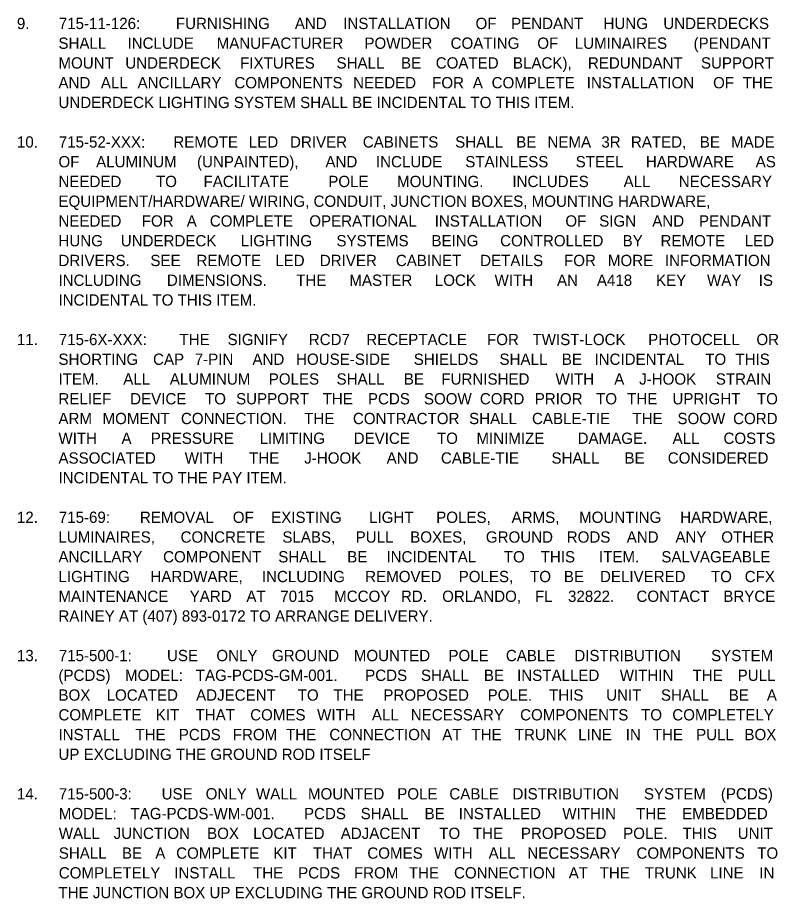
# Model space of a CAD drawing. Extents: x -55 to 2471539, y -90 to 3608906.
# Drawn here: x 544 to 1015, y 2826 to 3372 of the extents above; entities that cross this region are included whole.
import ezdxf

# ---------------------------------------------------------------- set-up
doc = ezdxf.new("R2010")
doc.units = 0
doc.layers.add('XSCell', color=7, linetype='Continuous')

msp = doc.modelspace()

# ---------------------------------------------------------------- texts
at = {"layer": 'XSCell'}
for s, p in [('9.', (543.22, 3365.2)), ('715-11-126: ', (569.17, 3365.2)), ('FURNISHING ', (641.75, 3365.2)), ('AND ', (715.49, 3365.2)), ('INSTALLATION ', (745.48, 3365.2)), ('OF ', (827.49, 3365.2)), ('PENDANT ', (849.52, 3365.2)), ('HUNG ', (906.82, 3365.2)), ('UNDERDECKS ', (943.89, 3365.2)), ('SHALL ', (568.97, 3352.95)), ('INCLUDE ', (611.77, 3352.95)), ('MANUFACTURER ', (667.02, 3352.95)), ('POWDER ', (758.61, 3352.95)), ('COATING ', (812.04, 3352.95)), ('OF ', (865.78, 3352.95)), ('LUMINAIRES ', (889.02, 3352.95)), ('(PENDANT ', (962.64, 3352.95)), ('MOUNT ', (568.97, 3340.7)), ('UNDERDECK ', (610.39, 3340.7)), ('FIXTURES ', (681.58, 3340.7)), ('SHALL ', (741.33, 3340.7)), ('BE ', (781.3, 3340.7)), ('COATED ', (802.82, 3340.7)), ('BLACK), ', (850.67, 3340.7)), ('REDUNDANT ', (897.15, 3340.7)), ('SUPPORT ', (967.21, 3340.7)), ('AND ', (568.97, 3328.45)), ('ALL ', (595.25, 3328.45)), ('ANCILLARY ', (618.01, 3328.45)), ('COMPONENTS ', (678.02, 3328.45)), ('NEEDED ', (751.63, 3328.45)), ('FOR ', (800.59, 3328.45)), ('A ', (825.8, 3328.45)), ('COMPLETE ', (837.47, 3328.45)), ('INSTALLATION ', (896.43, 3328.45)), ('OF ', (974.74, 3328.45)), ('THE ', (993.07, 3328.45)), ('UNDERDECK LIGHTING SYSTEM SHALL BE INCIDENTAL TO THIS ITEM.', (568.97, 3316.2)), ('10.', (543.22, 3291.7)), ('715-52-XXX: ', (569.17, 3291.7)), ('REMOTE ', (640.18, 3291.7)), ('LED ', (686.97, 3291.7)), ('DRIVER ', (712.5, 3291.7)), ('CABINETS ', (757.61, 3291.7)), ('SHALL ', (814.88, 3291.7)), ('BE ', (852.71, 3291.7)), ('NEMA ', (872.09, 3291.7)), ('3R ', (905.47, 3291.7)), ('RATED, ', (923.8, 3291.7)), ('BE ', (966.51, 3291.7)), ('MADE ', (985.89, 3291.7)), ('OF ', (568.97, 3279.45)), ('ALUMINUM ', (592.31, 3279.45)), ('(UNPAINTED), ', (654.86, 3279.45)), ('AND ', (734.47, 3279.45)), ('INCLUDE ', (765.76, 3279.45)), ('STAINLESS ', (821.12, 3279.45)), ('STEEL ', (889.55, 3279.45)), ('HARDWARE ', (933.07, 3279.45)), ('AS ', (1001.15, 3279.45)), ('NEEDED ', (568.97, 3267.2)), ('TO ', (629.41, 3267.2)), ('FACILITATE ', (658.89, 3267.2)), ('POLE ', (736.22, 3267.2)), ('MOUNTING. ', (778.86, 3267.2)), ('INCLUDES ', (850.34, 3267.2)), ('ALL ', (919.26, 3267.2)), ('NECESSARY ', (953.5, 3267.2)), ('EQUIPMENT/HARDWARE/ WIRING, CONDUIT, JUNCTION BOXES, MOUNTING HARDWARE, ', (568.97, 3254.95)), ('NEEDED ', (568.97, 3242.7)), ('FOR ', (620.6, 3242.7)), ('A ', (648.48, 3242.7)), ('COMPLETE ', (662.81, 3242.7)), ('OPERATIONAL ', (724.44, 3242.7)), ('INSTALLATION ', (802.19, 3242.7)), ('OF ', (883.17, 3242.7)), ('SIGN ', (904.17, 3242.7)), ('AND ', (937.04, 3242.7)), ('PENDANT ', (966, 3242.7)), ('HUNG ', (568.97, 3230.45)), ('UNDERDECK ', (607.59, 3230.45)), ('LIGHTING ', (681.96, 3230.45)), ('SYSTEMS ', (741.27, 3230.45)), ('BEING ', (800.17, 3230.45)), ('CONTROLLED ', (842.75, 3230.45)), ('BY ', (918.66, 3230.45)), ('REMOTE ', (942.16, 3230.45)), ('LED ', (994.28, 3230.45)), ('DRIVERS. ', (568.97, 3218.2)), ('SEE ', (625.96, 3218.2)), ('REMOTE ', (654.53, 3218.2)), ('LED ', (703.36, 3218.2)), ('DRIVER ', (730.96, 3218.2)), ('CABINET ', (778.11, 3218.2)), ('DETAILS ', (830.37, 3218.2)), ('FOR ', (882.35, 3218.2)), ('MORE ', (909.54, 3218.2)), ('INFORMATION ', (944.87, 3218.2)), ('INCLUDING ', (568.97, 3205.95)), ('DIMENSIONS. ', (636.19, 3205.95)), ('THE ', (716.33, 3205.95)), ('MASTER ', (749.29, 3205.95)), ('LOCK ', (802.27, 3205.95)), ('WITH ', (839.28, 3205.95)), ('AN ', (877.99, 3205.95)), ('A418 ', (902.72, 3205.95)), ('KEY ', (939.37, 3205.95)), ('WAY ', (970.96, 3205.95)), ('IS ', (1003.04, 3205.95)), ('INCIDENTAL TO THIS ITEM.', (568.97, 3193.7)), ('11.', (543.22, 3169.2)), ('715-6X-XXX: ', (569.17, 3169.2)), ('THE ', (643.98, 3169.2)), ('SIGNIFY ', (673.78, 3169.2)), ('RCD7 ', (724.14, 3169.2)), ('RECEPTACLE ', (759.78, 3169.2)), ('FOR ', (834.61, 3169.2)), ('TWIST-LOCK ', (862.8, 3169.2)), ('PHOTOCELL ', (934.54, 3169.2)), ('OR ', (1001.6, 3169.2)), ('SHORTING ', (568.97, 3156.95)), ('CAP ', (627.61, 3156.95)), ('7-PIN ', (653.44, 3156.95)), ('AND ', (689.22, 3156.95)), ('HOUSE-SIDE ', (716.26, 3156.95)), ('SHIELDS ', (789.21, 3156.95)), ('SHALL ', (842.34, 3156.95)), ('BE ', (880.99, 3156.95)), ('INCIDENTAL ', (901.2, 3156.95)), ('TO ', (969.85, 3156.95)), ('THIS ', (988.6, 3156.95)), ('ITEM. ', (568.97, 3144.7)), (' ALL ', (606.53, 3144.7)), ('ALUMINUM ', (637.99, 3144.7)), ('POLES ', (699.32, 3144.7)), ('SHALL ', (741.36, 3144.7)), ('BE ', (783.06, 3144.7)), ('FURNISHED ', (806.31, 3144.7)), ('WITH ', (877.09, 3144.7)), ('A ', (913.46, 3144.7)), ('J-HOOK ', (928.92, 3144.7)), ('STRAIN ', (976.44, 3144.7)), ('RELIEF ', (568.97, 3132.45)), ('DEVICE ', (613.42, 3132.45)), ('TO ', (659.81, 3132.45)), ('SUPPORT ', (679.06, 3132.45)), ('THE ', (732.71, 3132.45)), ('PCDS ', (760.8, 3132.45)), ('SOOW ', (795.5, 3132.45)), ('CORD ', (830.19, 3132.45)), ('PRIOR ', (864.19, 3132.45)), ('TO ', (902.22, 3132.45)), ('THE ', (921.47, 3132.45)), ('UPRIGHT ', (949.56, 3132.45)), ('TO ', (1001.9, 3132.45)), ('ARM ', (568.97, 3120.2)), ('MOMENT ', (596.3, 3120.2)), ('CONNECTION. ', (644.89, 3120.2)), (' THE ', (718.68, 3120.2)), ('CONTRACTOR ', (751.49, 3120.2)), ('SHALL ', (823.52, 3120.2)), ('CABLE-TIE ', (862.5, 3120.2)), ('THE ', (924.76, 3120.2)), ('SOOW ', (952.66, 3120.2)), ('CORD ', (987.15, 3120.2)), ('WITH ', (568.97, 3107.95)), ('A ', (608.02, 3107.95)), ('PRESSURE ', (626.17, 3107.95)), ('LIMITING ', (693.65, 3107.95)), ('DEVICE ', (751.97, 3107.95)), ('TO ', (803.57, 3107.95)), ('MINIMIZE ', (828.05, 3107.95)), ('DAMAGE. ', (890.76, 3107.95)), (' ALL ', (947.04, 3107.95)), ('COSTS ', (981.18, 3107.95)), ('ASSOCIATED ', (568.97, 3095.7)), ('WITH ', (647.21, 3095.7)), ('THE ', (687.14, 3095.7)), ('J-HOOK ', (721.32, 3095.7)), ('AND ', (772.4, 3095.7)), ('CABLE-TIE ', (806.04, 3095.7)), ('SHALL ', (874.58, 3095.7)), ('BE ', (919.84, 3095.7)), ('CONSIDERED ', (946.65, 3095.7)), ('INCIDENTAL TO THE PAY ITEM.', (568.97, 3083.45)), ('12.', (543.22, 3058.95)), ('715-69: ', (569.17, 3058.95)), ('REMOVAL ', (619.46, 3058.95)), ('OF ', (677.04, 3058.95)), ('EXISTING ', (700.81, 3058.95)), ('LIGHT ', (761.5, 3058.95)), ('POLES, ', (803.11, 3058.95)), ('ARMS, ', (849.85, 3058.95)), ('MOUNTING ', (891.68, 3058.95)), ('HARDWARE, ', (954.35, 3058.95)), ('LUMINAIRES, ', (568.97, 3046.7)), ('CONCRETE ', (644.66, 3046.7)), ('SLABS, ', (707.77, 3046.7)), ('PULL ', (753.18, 3046.7)), ('BOXES, ', (787, 3046.7)), ('GROUND ', (833.9, 3046.7)), ('RODS ', (884.03, 3046.7)), ('AND ', (921.2, 3046.7)), ('ANY ', (951.39, 3046.7)), ('OTHER ', (979.82, 3046.7)), ('ANCILLARY ', (568.97, 3034.45)), ('COMPONENT ', (633.83, 3034.45)), ('SHALL ', (705.2, 3034.45)), ('BE ', (747.96, 3034.45)), ('INCIDENTAL ', (772.27, 3034.45)), ('TO ', (845.03, 3034.45)), ('THIS ', (867.87, 3034.45)), ('ITEM. ', (904.02, 3034.45)), ('SALVAGEABLE ', (942.65, 3034.45)), ('LIGHTING ', (568.97, 3022.2)), ('HARDWARE, ', (625.97, 3022.2)), ('INCLUDING ', (695.05, 3022.2)), ('REMOVED ', (759.09, 3022.2)), ('POLES, ', (817.05, 3022.2)), ('TO ', (861.3, 3022.2)), ('BE ', (882.24, 3022.2)), ('DELIVERED ', (904.65, 3022.2)), ('TO ', (973.41, 3022.2)), ('CFX ', (994.35, 3022.2)), ('MAINTENANCE ', (568.97, 3009.95)), ('YARD ', (650.31, 3009.95)), ('AT ', (685.46, 3009.95)), ('7015 ', (706.48, 3009.95)), ('MCCOY ', (739.86, 3009.95)), ('RD. ', (781.25, 3009.95)), ('ORLANDO, ', (806.81, 3009.95)), ('FL ', (864.31, 3009.95)), ('32822. ', (884.82, 3009.95)), ('CONTACT ', (927.24, 3009.95)), ('BRYCE ', (981.07, 3009.95)), ('RAINEY AT (407) 893-0172 TO ARRANGE DELIVERY.', (568.97, 2997.7)), ('13.', (543.22, 2973.2)), ('715-500-1: ', (569.17, 2973.2)), ('USE ', (636.23, 2973.2)), ('ONLY ', (666.85, 2973.2)), ('GROUND ', (701.34, 2973.2)), ('MOUNTED ', (752.04, 2973.2)), ('POLE ', (810.68, 2973.2)), ('CABLE ', (846.3, 2973.2)), ('DISTRIBUTION ', (888.74, 2973.2)), ('SYSTEM ', (973.52, 2973.2)), ('(PCDS) ', (568.97, 2960.95)), ('MODEL: ', (610.23, 2960.95)), ('TAG-PCDS-GM-001. ', (654.09, 2960.95)), ('PCDS ', (759.09, 2960.95)), ('SHALL ', (793.65, 2960.95)), ('BE ', (832.67, 2960.95)), ('INSTALLED ', (853.25, 2960.95)), ('WITHIN ', (916.87, 2960.95)), ('THE ', (962.03, 2960.95)), ('PULL ', (989.98, 2960.95)), ('BOX ', (568.97, 2948.7)), ('LOCATED ', (598.82, 2948.7)), ('ADJECENT ', (654.29, 2948.7)), ('TO ', (717.27, 2948.7)), ('THE ', (739.4, 2948.7)), ('PROPOSED ', (770.36, 2948.7)), ('POLE. ', (834.98, 2948.7)), ('THIS ', (873.04, 2948.7)), ('UNIT ', (908.47, 2948.7)), ('SHALL ', (942.4, 2948.7)), ('BE ', (984.44, 2948.7)), ('A ', (1008.04, 2948.7)), ('COMPLETE ', (568.97, 2936.45)), ('KIT ', (629.29, 2936.45)), ('THAT ', (653.96, 2936.45)), ('COMES ', (687.81, 2936.45)), ('WITH ', (729.3, 2936.45)), ('ALL ', (763.24, 2936.45)), ('NECESSARY ', (787.36, 2936.45)), ('COMPONENTS ', (855.13, 2936.45)), ('TO ', (930.1, 2936.45)), ('COMPLETELY ', (949.45, 2936.45)), ('INSTALL ', (568.97, 2924.2)), ('THE ', (616.69, 2924.2)), ('PCDS ', (643.55, 2924.2)), ('FROM ', (677.03, 2924.2)), ('THE ', (710.01, 2924.2)), ('CONNECTION ', (736.88, 2924.2)), ('AT ', (806.88, 2924.2)), ('THE ', (824.96, 2924.2)), ('TRUNK ', (851.82, 2924.2)), ('LINE ', (891.16, 2924.2)), ('IN ', (920.6, 2924.2)), ('THE ', (937.35, 2924.2)), ('PULL ', (964.22, 2924.2)), ('BOX ', (994.18, 2924.2)), ('UP EXCLUDING THE GROUND ROD ITSELF', (568.97, 2911.95)), ('14.', (543.22, 2887.45)), ('715-500-3: ', (569.17, 2887.45)), ('USE ', (632.91, 2887.45)), ('ONLY ', (660.21, 2887.45)), ('WALL ', (691.38, 2887.45)), ('MOUNTED ', (723.64, 2887.45)), ('POLE ', (778.96, 2887.45)), ('CABLE ', (811.26, 2887.45)), ('DISTRIBUTION ', (850.39, 2887.45)), ('SYSTEM ', (931.85, 2887.45)), ('(PCDS) ', (979.56, 2887.45)), ('MODEL: ', (569.17, 2875.2)), ('TAG-PCDS-WM-001. ', (613.61, 2875.2)), ('PCDS ', (721.15, 2875.2)), ('SHALL ', (756.3, 2875.2)), ('BE ', (795.91, 2875.2)), ('INSTALLED ', (817.08, 2875.2)), ('WITHIN ', (881.29, 2875.2)), ('THE ', (927.04, 2875.2)), ('EMBEDDED ', (955.58, 2875.2)), ('WALL ', (569.17, 2862.95)), ('JUNCTION ', (603.18, 2862.95)), ('BOX ', (661.1, 2862.95)), ('LOCATED ', (689.71, 2862.95)), ('ADJACENT ', (743.95, 2862.95)), ('TO ', (804.98, 2862.95)), ('THE ', (825.87, 2862.95)), ('PROPOSED ', (855.59, 2862.95)), ('POLE. ', (918.98, 2862.95)), ('THIS ', (955.8, 2862.95)), ('UNIT ', (990, 2862.95)), ('SHALL ', (569.17, 2850.7)), ('BE ', (608.32, 2850.7)), ('A ', (629.02, 2850.7)), ('COMPLETE ', (641.93, 2850.7)), ('KIT ', (702.14, 2850.7)), ('THAT ', (726.69, 2850.7)), ('COMES ', (760.42, 2850.7)), ('WITH ', (801.78, 2850.7)), ('ALL ', (835.61, 2850.7)), ('NECESSARY ', (859.61, 2850.7)), ('COMPONENTS ', (927.25, 2850.7)), ('TO ', (1002.1, 2850.7)), ('COMPLETELY ', (569.17, 2838.45)), ('INSTALL ', (640.75, 2838.45)), ('THE ', (689.57, 2838.45)), ('PCDS ', (717.54, 2838.45)), ('FROM ', (752.12, 2838.45)), ('THE ', (786.19, 2838.45)), ('CONNECTION ', (814.16, 2838.45)), ('AT ', (885.26, 2838.45)), ('THE ', (904.44, 2838.45)), ('TRUNK ', (932.41, 2838.45)), ('LINE ', (972.85, 2838.45)), ('IN ', (1003.39, 2838.45)), ('THE JUNCTION BOX UP EXCLUDING THE GROUND ROD ITSELF. ', (568.97, 2826.2))]:
    msp.add_text(s, height=7, dxfattribs=at).set_placement(p)

doc.saveas('drawing.dxf')
